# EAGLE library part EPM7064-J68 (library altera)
EPM7064 MAX 7000 family
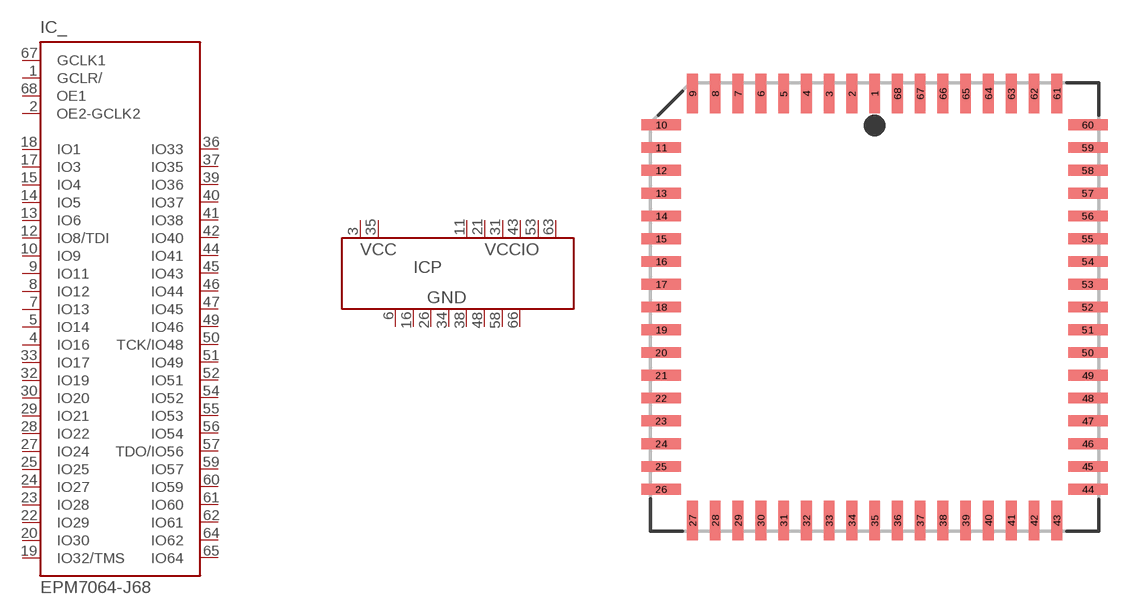
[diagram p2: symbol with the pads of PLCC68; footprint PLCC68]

Designator prefix IC; gates P=PWR8-2-6 _=7064-68

## EPM7064-J68 (OC_FARNELL: unknown; OC_NEWARK: unknown)  [PLCC68]
1  _:GCLR/  in
2  _:OE2-GCLK2  in
3  P:VCC  pwr
4  _:IO16
5  _:IO14
6  P:GND  pwr
7  _:IO13
8  _:IO12
9  _:IO11
10  _:IO9
11  P:VCCIO  pwr
12  _:IO8/TDI
13  _:IO6
14  _:IO5
15  _:IO4
16  P:GND  pwr
17  _:IO3
18  _:IO1
19  _:IO32/TMS
20  _:IO30
21  P:VCCIO  pwr
22  _:IO29
23  _:IO28
24  _:IO27
25  _:IO25
26  P:GND  pwr
27  _:IO24
28  _:IO22
29  _:IO21
30  _:IO20
31  P:VCCIO  pwr
32  _:IO19
33  _:IO17
34  P:GND  pwr
35  P:VCC  pwr
36  _:IO33
37  _:IO35
38  P:GND  pwr
39  _:IO36
40  _:IO37
41  _:IO38
42  _:IO40
43  P:VCCIO  pwr
44  _:IO41
45  _:IO43
46  _:IO44
47  _:IO45
48  P:GND  pwr
49  _:IO46
50  _:TCK/IO48
51  _:IO49
52  _:IO51
53  P:VCCIO  pwr
54  _:IO52
55  _:IO53
56  _:IO54
57  _:TDO/IO56
58  P:GND  pwr
59  _:IO57
60  _:IO59
61  _:IO60
62  _:IO61
63  P:VCCIO  pwr
64  _:IO62
65  _:IO64
66  P:GND  pwr
67  _:GCLK1  in
68  _:OE1  in

## Footprint PLCC68 (pad centres in mm)
Plastic J-Lead Chip Carrier
smd 0.6 x 2.2: 1 0,11.9; 2 -1.27,11.9; 3 -2.54,11.9; 4 -3.81,11.9; 5 -5.08,11.9; 6 -6.35,11.9; 7 -7.62,11.9; 8 -8.89,11.9; 9 -10.16,11.9; 27 -10.16,-11.9; 28 -8.89,-11.9; 29 -7.62,-11.9; 30 -6.35,-11.9; 31 -5.08,-11.9; 32 -3.81,-11.9; 33 -2.54,-11.9; 34 -1.27,-11.9; 35 0,-11.9; 36 1.27,-11.9; 37 2.54,-11.9; 38 3.81,-11.9; 39 5.08,-11.9; 40 6.35,-11.9; 41 7.62,-11.9; 42 8.89,-11.9; 43 10.16,-11.9; 61 10.16,11.9; 62 8.89,11.9; 63 7.62,11.9; 64 6.35,11.9; 65 5.08,11.9; 66 3.81,11.9; 67 2.54,11.9; 68 1.27,11.9
smd 2.2 x 0.6: 10 -11.9,10.16; 11 -11.9,8.89; 12 -11.9,7.62; 13 -11.9,6.35; 14 -11.9,5.08; 15 -11.9,3.81; 16 -11.9,2.54; 17 -11.9,1.27; 18 -11.9,0; 19 -11.9,-1.27; 20 -11.9,-2.54; 21 -11.9,-3.81; 22 -11.9,-5.08; 23 -11.9,-6.35; 24 -11.9,-7.62; 25 -11.9,-8.89; 26 -11.9,-10.16; 44 11.9,-10.16; 45 11.9,-8.89; 46 11.9,-7.62; 47 11.9,-6.35; 48 11.9,-5.08; 49 11.9,-3.81; 50 11.9,-2.54; 51 11.9,-1.27; 52 11.9,0; 53 11.9,1.27; 54 11.9,2.54; 55 11.9,3.81; 56 11.9,5.08; 57 11.9,6.35; 58 11.9,7.62; 59 11.9,8.89; 60 11.9,10.16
